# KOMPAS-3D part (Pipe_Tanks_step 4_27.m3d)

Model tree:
1. X Axis
2. Y Axis
3. Z Axis  (labels: Pipe Dn 20; Valve Dy 50)
     Òîëùèíà ñòåíêè 1 = 1

Referenced files in C:\Documents and Settings\kashirsky\Мои документы\Camtasia Studio\Pipelines3D\Tanks\: Tanks_step 4.a3d
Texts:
  Pipe Dn 20
  Steel ASTM A295
  Three Point Plane
  Plane at Angle
  Line and Point Plane
  Axis through Two Vertices
  Axis of Feature
  Axis of Conical Surface
  Axis through Edge
  Trim by Surface
  Trim by Sketch
  Feature with No History
  Intersection Axis of Two Planes
  Two Line Plane
  Line and Face Plane
  Bend by line
  Hole in sheet body
  Cut in sheet body
  Point in CM
  Linear Dimension from Line to Point
  Surface Finish Symbol
  Geometric Tolerance Symbol
  Leader #1
  Leader #2
  Leader #3
  Shape Deviations and Datum
  Node point number
  Mark of coordination axis
  Node point designation
  Mark/Reference designation with leader
  Mark/reference designation on line
  Mark/Reference designation without leader
  Valve Dy 50
  Plane of section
